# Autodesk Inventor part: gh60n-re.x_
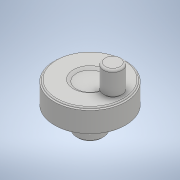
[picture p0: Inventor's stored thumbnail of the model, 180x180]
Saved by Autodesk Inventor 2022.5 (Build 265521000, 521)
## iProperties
Part Number: gh60n-re.x_
Material: 一般
Document SubType Name: Modeling
Designer: ImaoCorp
Density: 1 g/cm^3
Appearance: 既定
Sending System: SOLIDWORKS 2017-2017317
MC: AMD64
MC_MODEL: Intel64 Family 6 Model 60 Stepping 3, GenuineIntel
OS: Windows_NT
FRU: Parasolid Version 29.0, build 201,  4-17-2017
FORMAT: text
GUISE: transmit
KEY: gh60n-re
FILE: gh60n-re.x_t
DATE: Mon Jul 01 17:32:20 2019
Author: ImaoCorp
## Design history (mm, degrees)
feature "Base1"
node "ソリッド1"
